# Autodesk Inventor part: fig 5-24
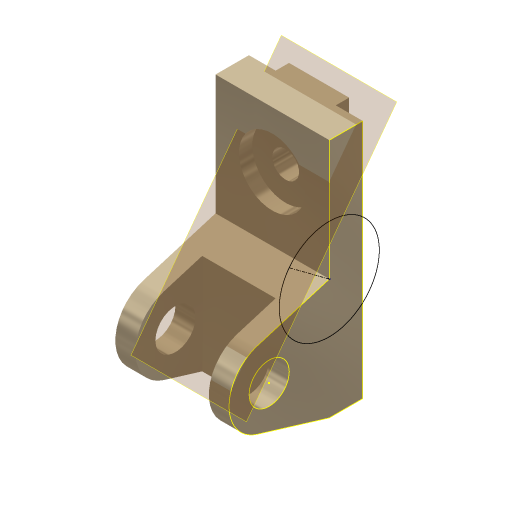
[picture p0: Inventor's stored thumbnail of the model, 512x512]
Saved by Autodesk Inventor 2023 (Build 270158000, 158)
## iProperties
Created: 2001-11
Part Number: fig 5-24
Document SubType Name: Modeling
Designer: Renu Muthoo
Density: 1 g/cm^3
Material: Generic
Appearance: Metal-Titanium (Polished)
Control State: 0
Master: False
Checked Out: False
Shininess: 65.0
Angle Display Precision: 2
Document Length Units: 11269
Document Angle Units: 11279
Document Time Units: 11290
Document Mass Units: 11283
Document Length Units Precision: 3
Document Angle Units Precision: 2
Compacted: False
Density: 0.0
Volumn: 0.0
Area: 0.0
PropertySet Name: Model Information
Author: Renu Muthoo
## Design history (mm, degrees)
node "Sketch1"
sketch "Sketch2"
  geometry: L1 (33.257, 104.664)-(33.257, -75.336); L2 (33.257, -75.336)-(8.257, -75.336); L3 (8.257, -75.336)-(-45.451, -59.045); L4 (-45.451, -1.628)-(8.257, 14.664); L5 (8.257, 14.664)-(8.257, 104.664); L6 (8.257, 104.664)-(33.257, 104.664); C1 r 15 at (-36.743, -30.336); A1 r 30 centre (-36.743, -30.336) between (-45.451, -1.628) and (-45.451, -59.045)
  constraints: 12 end point, 2 centre point, 2 equal length, 2 parallel, 2 point on circle, 2 tangent, 1 coincident, 1 perpendicular, 1 vertical
  dimensions: "d0" = 180 distance of L1.start L1.end; "d1" = 30 radius of A1; "d2" = 25 distance of L5.end L1.start; "d3" = 45 distance from line of L2 A1.centre; "d4" = 70 distance from line of L1 A1.centre; "d5" = 30 diameter of C1
extrude "Extrusion1" new body sketch "Sketch2" distance "d6" = 85; taper "d7" = 0 deg
workplane "Work Plane1"
sketch "Sketch3"
  geometry: L1 (15, 62.364)-(70, 62.364); L2 (70, 62.364)-(70, -52.386); L3 (70, -52.386)-(15, -52.386); L4 (15, -52.386)-(15, 62.364); L5 (0, -45)-(0, -28.708) reference
  constraints: 8 end point, 2 parallel, 1 horizontal, 1 perpendicular
  dimensions: "d8" = 55 distance of L1.start L1.end; "d9" = 15 distance between parallel lines of L5 L4
extrude "Extrusion2" cut sketch "Sketch3" distance "d10" = 50; taper "d11" = 0 deg
sketch "Sketch4"
  geometry: L1 (0, 25)-(85, 25) reference; L2 (0, 0)-(0, 25) reference; L3 (20, 25)-(65, 25); L4 (65, 25)-(65, 35); L5 (65, 35)-(20, 35); L6 (20, 35)-(20, 25)
  constraints: 8 end point, 2 parallel, 1 horizontal, 1 perpendicular, 1 point on line
  dimensions: "d12" = 45 distance of L4.end L5.end; "d13" = 10 distance of L3.end L4.end; "d14" = 20 distance between parallel lines of L2 L6
extrude "Extrusion3" join sketch "Sketch4" stored distance "d15" = 50; taper "d16" = 0 deg
sketch "Sketch5"
  geometry: L1 (85, 0)-(85, 90) reference; L2 (0, 90)-(85, 90) reference; 1 further point
  dimensions: "d17" = 42 distance from line of L2 point (42.5, 48); "d18" = 42.5 distance from line of L1 point (42.5, 48)
hole "Hole1" sketch "Sketch5" at (42.5, 48) diameter "d19" = 20; stored, may be unused: countersink angle "d23" = 82 deg, drill point angle "d25" = 118 deg; dims "d20" = 6, "d21" = 50, "d22" = 10, "d24" = 8
sketch "Sketch8"
  geometry: L1 (75.336, 33.257)-(75.336, 8.257) reference; L2 (-104.664, 33.257)-(75.336, 33.257) reference; L3 (-104.664, 8.257)-(-104.664, 33.257) reference; L4 (-14.664, 8.257)-(-104.664, 8.257) reference; L5 (1.628, -45.451)-(-14.664, 8.257) reference; L6 (75.336, 8.257)-(59.045, -45.451) reference; C1 r 15 at (30.336, -36.743) reference; C2 r 37.437 at (-14.664, 8.257); A1 r 30 centre (30.336, -36.743) between (1.628, -45.451) and (59.045, -45.451) reference
  constraints: 1 centre point, 1 coincident
sketch "Sketch9"
  geometry: L1 (75.336, 33.257)-(75.336, 8.257) reference; L2 (-14.664, 8.257)-(-104.664, 8.257) reference; L3 (1.628, -45.451)-(-14.664, 8.257) reference; L4 (75.336, 8.257)-(59.045, -45.451) reference; L5 (-14.664, 8.257)-(-37, -21.743); C1 r 15 at (30.336, -36.743) reference; A1 r 30 centre (30.336, -36.743) between (1.628, -45.451) and (59.045, -45.451) reference
  constraints: 2 end point
workplane "Work Plane11"
body "Solid1"
